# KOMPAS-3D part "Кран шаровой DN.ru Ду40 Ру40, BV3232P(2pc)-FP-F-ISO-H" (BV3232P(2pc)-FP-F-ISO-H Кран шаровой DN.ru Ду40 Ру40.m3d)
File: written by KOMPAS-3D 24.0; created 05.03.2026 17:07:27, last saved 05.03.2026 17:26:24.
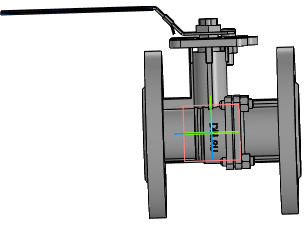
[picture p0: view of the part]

Document properties: Автор: R2D2; Полное имя файла: BV3232P(2pc)-FP-F-ISO-H Кран шаровой DN.ru Ду40 Ру40.cdw

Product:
- Part/product: Кран шаровой DN.ru Ду40 Ру40  | designation BV3232P(2pc)-FP-F-ISO-H
    Масса: 6.49
    Раздел спецификации: Прочие изделия
    Форматы листов документа: A2
    Примечание: D160-22133

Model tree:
1. Операция без истории:2

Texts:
  BV3232P(2pc)-FP-F-ISO-H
